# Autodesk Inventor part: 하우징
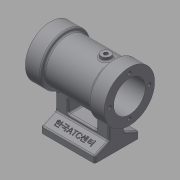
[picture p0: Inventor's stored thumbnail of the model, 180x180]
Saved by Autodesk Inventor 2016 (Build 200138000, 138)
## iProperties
Created: 2018-01
Part Number: 하우징
Material: 알루미늄 6061
Document SubType Name: Modeling
Designer: mduedu
Density: 2.71 g/cm^3
Appearance: 기본값
Mass: 74.6911 g
Surface Area: 127.588 cm^2
Volume: 27.5613 cm^3
Author: mduedu
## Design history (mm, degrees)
sketch "스케치1"
  geometry: L1 (-25, 0)-(25, 0); L2 (-25, 0)-(-25, 16); L3 (-25, 16)-(-15, 16); L4 (-15, 16)-(-15, 14); L5 (-15, 14)-(15, 14); L6 (15, 14)-(15, 16); L7 (15, 16)-(25, 16); L8 (25, 16)-(25, 0); 2 further points
  constraints: 16 end point, 3 parallel, 2 collinear, 2 perpendicular, 1 coincident, 1 horizontal, 1 midpoint, 1 vertical
  dimensions: "d0" = 50 distance of L1.start L1.end; "d2" = 10 distance of L2.end L3.end; "d3" = 10 distance of L6.end L7.end (= d2); "d4" = 32 diameter of L3 L1; "d5" = 28 diameter of L5 L1
revolve "회전1" sketch "스케치1" stored, may be unused: angle "d6" = 90 deg
hole "구멍1" diameter "d9" = 20; stored, may be unused: countersink angle "d13" = 90 deg, drill point angle "d15" = 118 deg; dims "d7" = 10, "d8" = 10, "d10" = 6, "d11" = 4, "d12" = 2, "d14" = 8
fillet "모깎기1" dims "d16" = 1
sketch "스케치2"
  geometry: L1 (0, 0)-(-34, 0); L2 (-34, 14)-(-34, -14); L3 (-34, 14)-(-30, 14); L4 (-30, 14)-(-26, 5); L5 (-26, 5)-(-13.077, 5); L6 (-26, -5)-(-13.077, -5); L7 (-30, -14)-(-26, -5); L8 (-34, -14)-(-30, -14); C1 r 10 at (0, 0) reference; A1 r 14 centre (0, 0) between (-13.077, 5) and (-13.077, -5); 2 further points
  constraints: 16 end point, 3 symmetric about line, 2 perpendicular, 2 point on circle, 1 centre point, 1 coincident, 1 horizontal, 1 midpoint, 1 parallel, 2 other
  dimensions: "d17" = 34 distance of L1.end L1.start; "d18" = 28 distance between parallel lines of L8 L3; "d19" = 10 distance between parallel lines of L6 L5; "d20" = 4 distance of L2.end L7.start; "d21" = 8 distance from line of L6.start L2
extrude "돌출1" join sketch "스케치2" stored distance "d22" = 34; taper "d23" = 0 deg
sketch "스케치3"
  geometry: L1 (-9, -16)-(9, -16); L2 (9, -16)-(9, -24); L3 (9, -24)-(-9, -24); L4 (-9, -24)-(-9, -16); L5 (-17, -15.199)-(-17, -26) reference; L6 (17, -26)-(17, -15.199) reference; L7 (-17, -34)-(17, -34) reference; 1 further point
  constraints: 8 end point, 2 parallel, 1 horizontal, 1 perpendicular
  dimensions: "d24" = 8 distance between parallel lines of L4 L5; "d25" = 8 distance between parallel lines of L2 L6; "d26" = 10 distance between parallel lines of L3 L7; "d27" = 8 distance of L1.end L2.end
extrude "돌출2" cut sketch "스케치3" stored distance "d28" = 34; taper "d29" = 0 deg
fillet "모깎기2" dims "d30" = 1
fillet "모깎기3" dims "d31" = 1
fillet "모깎기4" dims "d32" = 1
fillet "모깎기5" dims "d33" = 1
fillet "모깎기6" dims "d34" = 1
sketch "스케치4"
  geometry: 4 further points
  constraints: 4 other
hole "구멍2" sketch "스케치4" at (-12.5, 0), (0, -12.5), (12.5, 0), (0, 12.5) diameter "d35" = 2.459; stored, may be unused: countersink angle "d39" = 90 deg, drill point angle "d41" = 120 deg; dims "d36" = 5.5, "d37" = 4, "d38" = 2, "d40" = 7
sketch "스케치5"
  geometry: 4 further points
  constraints: 4 other
hole "구멍4" sketch "스케치5" at (-12.5, 0), (0, -12.5), (12.5, 0), (0, 12.5) diameter "d42" = 2.459; stored, may be unused: countersink angle "d46" = 90 deg, drill point angle "d48" = 120 deg; dims "d43" = 5.5, "d44" = 4, "d45" = 2, "d47" = 7
sketch "스케치6"
  geometry: 2 further points
  constraints: 2 other
hole "구멍5" sketch "스케치6" at (7, 14), (25, 14) diameter "d49" = 2.459; stored, may be unused: countersink angle "d53" = 90 deg, drill point angle "d55" = 120 deg; dims "d50" = 6.9, "d51" = 4, "d52" = 2, "d54" = 8.4
node "작업 평면1"
sketch "스케치7"
  geometry: L1 (-25, 16)-(-25, -16) reference; C1 r 3 at (-10, 0); 1 further point
  constraints: 1 centre point, 1 horizontal alignment
  dimensions: "d57" = 6 diameter of C1; "d60" = 15 distance from line of C1.centre L1
extrude "돌출3" join sketch "스케치7" stored distance "d61" = 10; taper "d62" = 0 deg
fillet "모깎기7" dims "d63" = 1
hole "구멍6" diameter "d66" = 2.459; stored, may be unused: countersink angle "d70" = 90 deg, drill point angle "d72" = 118 deg; dims "d64" = 10, "d65" = 10, "d67" = 6, "d68" = 4, "d69" = 2, "d71" = 8
sketch "스케치8"
  geometry: L1 (-1, 0)-(0, 0) reference; L2 (0, 0)-(0, 8.549) reference; L3 (0, 8.549)-(-1, 8.549) reference; L4 (-1, 8.549)-(-1, 0) reference; L5 (32, 0)-(33, 0) reference; L6 (33, 0)-(33, 8.549) reference; L7 (32, 8.549)-(33, 8.549) reference; L8 (32, 8.549)-(32, 0) reference; 3 further points
  constraints: 1 horizontal alignment, 1 midpoint, 1 vertical alignment, 1 other
feature "엠보싱1" sketch "스케치8" dims "d73" = 0.5, "d74" = 0
node "솔리드1"
node "투영된 루프1"
node "투영된 루프2"
node "절단 모서리 투영1"
other parameters: "d56" = 16
